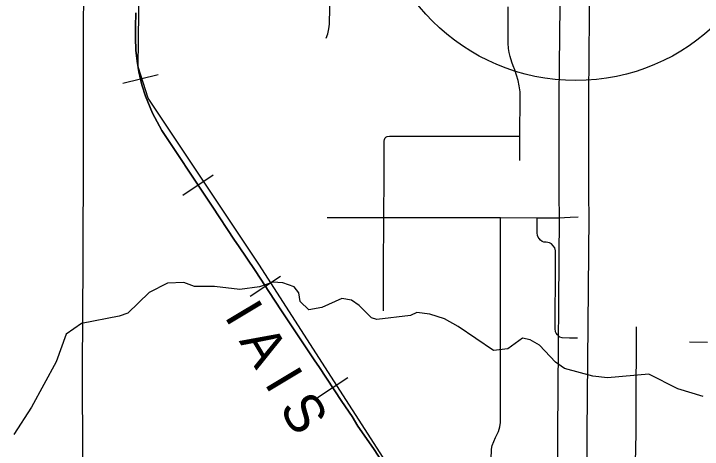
# Model space of a CAD drawing. Extents: x -1403959 to 81668, y -1400582 to 11018.
# Drawn here: x 6303.2 to 6440.3, y 8721.4 to 8808.1 of the extents above; entities that cross this region are included whole.
import ezdxf

# ---------------------------------------------------------------- set-up
doc = ezdxf.new("R2010")
doc.units = 0
for name, color, linetype in [('tdCiCityCuldesac', 7, 'Continuous'), ('tdCiSectNmbr', 7, 'Continuous'), ('tdCiSectTwpRng', 7, 'Continuous'), ('tdCoDivCarto', 7, 'Continuous'), ('tdCoSecRteBand', 7, 'Continuous'), ('tdCoSurfAsphalt', 7, 'Continuous'), ('tdCoSurfBitum', 7, 'Continuous')]:
    doc.layers.add(name, color=color, linetype=linetype)

msp = doc.modelspace()

# ---------------------------------------------------------------- linework, layer by layer
at = {"layer": 'tdCiSectNmbr'}
msp.add_lwpolyline([(6316.8, 8675.61), (6316.83, 8694.07), (6316.92, 8715.95), (6316.98, 8719.23), (6316.86, 8737.37), (6317.01, 8758.73), (6317.06, 8780.66), (6317.12, 8801.37), (6317.15, 8815.99), (6317.15, 8837.27), (6317.09, 8857.46), (6317.02, 8863.89)], dxfattribs=at)
at = {"layer": 'tdCiSectTwpRng'}
for points in [[(6365.44, 8803.2), (6365.73, 8804.09), (6365.95, 8805.05), (6366.08, 8806), (6366.28, 8815.68)], [(6404.02, 8791.51), (6404.02, 8792.55), (6403.84, 8793.75), (6403.65, 8794.82), (6403.35, 8795.85), (6402.99, 8796.9), (6402.64, 8797.71), (6402.37, 8798.45), (6402.03, 8799.54), (6401.84, 8800.39), (6401.75, 8801.18), (6401.63, 8802.23), (6401.68, 8809.45)], [(6404, 8778.87), (6404, 8783.7), (6404.02, 8791.51)], [(6376.94, 8775.69), (6376.99, 8782.7), (6377.03, 8783.03), (6377.17, 8783.37)], [(6377.17, 8783.37), (6377.33, 8783.52), (6377.59, 8783.68), (6378.03, 8783.75), (6381.98, 8783.75)], [(6381.98, 8783.75), (6404, 8783.7)], [(6376.93, 8767.55), (6376.94, 8775.63)], [(6365.64, 8767.55), (6376.93, 8767.55), (6400.13, 8767.56), (6407.43, 8767.49), (6409.61, 8767.47)], [(6376.82, 8748.97), (6376.84, 8757.17), (6376.93, 8767.55)], [(6398.28, 8719.4), (6398.34, 8721.44), (6398.46, 8722.17), (6399.15, 8723.76), (6399.71, 8724.94), (6400.02, 8725.89), (6400.1, 8726.74), (6400.13, 8767.56)], [(6407.43, 8767.49), (6407.43, 8767.49)], [(6415.5, 8743.53), (6413.88, 8743.55), (6412.39, 8743.6), (6411.96, 8743.75), (6411.72, 8743.93), (6411.47, 8744.18), (6411.25, 8744.5), (6411.11, 8744.79), (6411.04, 8745.45), (6411.08, 8757.89), (6411.09, 8760.92), (6410.95, 8761.52), (6410.64, 8761.93), (6410.3, 8762.3), (6409.9, 8762.51), (6409.23, 8762.61), (6408.76, 8762.64), (6408.41, 8762.76), (6408.12, 8763.02), (6407.84, 8763.33), (6407.62, 8763.65), (6407.5, 8763.96), (6407.45, 8764.48), (6407.43, 8767.49)], [(6409.61, 8767.47), (6411.74, 8767.48), (6413.99, 8767.62)], [(6413.99, 8767.62), (6415.6, 8767.66)], [(6427.18, 8733.73), (6427.21, 8741.1), (6427.23, 8745.8)], [(6437.76, 8742.79), (6441.35, 8742.76)], [(6427.04, 8719.37), (6427.08, 8721.02), (6427.14, 8725.24), (6427.17, 8732.18), (6427.18, 8733.73)]]:
    msp.add_lwpolyline(points, dxfattribs=at)
at = {"layer": 'tdCoDivCarto'}
for points in [[(6415.44, 8658.23), (6412.93, 8662), (6411.79, 8664.48), (6411.25, 8666.46), (6410.9, 8669.04), (6410.83, 8672.42), (6410.8, 8683.83), (6411.47, 8713.91), (6411.54, 8724.79), (6411.91, 8767.71), (6411.84, 8771.71), (6411.84, 8791.72), (6412.06, 8815.72)], [(6417.87, 8815.64), (6417.64, 8791.69), (6417.64, 8771.75), (6417.72, 8767.64), (6417.34, 8724.77), (6417.27, 8713.82), (6416.61, 8683.77), (6416.64, 8672.51), (6416.76, 8668.62), (6417.3, 8666.34), (6417.9, 8665.01), (6419.58, 8662.5)]]:
    msp.add_lwpolyline(points, dxfattribs=at)
at = {"layer": 'tdCoSecRteBand'}
for p, q in [((6324.9, 8794.24), (6331.95, 8795.97)), ((6336.89, 8771.98), (6342.92, 8776.01)), ((6350.27, 8751.88), (6356.34, 8755.85)), ((6363.67, 8731.75), (6369.74, 8735.73))]:
    msp.add_line(p, q, dxfattribs=at)
for points in [[(6408.58, 8670.42), (6352.02, 8758.22), (6329.97, 8791.27), (6328, 8797.53), (6328.6, 8846.39), (6327.94, 8883.79)], [(6379.69, 8714.18), (6374.81, 8721.61), (6371.72, 8726.04), (6370.62, 8727.95), (6368.54, 8730.94), (6363.97, 8737.91), (6363.13, 8739.03), (6360.79, 8742.58), (6356.68, 8748.76), (6355.12, 8751.08), (6351.25, 8757.01), (6347.95, 8761.88), (6347.17, 8763.02), (6342.72, 8769.79), (6339.78, 8774.19), (6334.69, 8781.86), (6332.72, 8784.84), (6330.82, 8788.32), (6329.43, 8791.65), (6328.72, 8793.91), (6328.08, 8796.51), (6327.78, 8798.61), (6327.48, 8800.84), (6327.43, 8803.27), (6327.45, 8805.48), (6327.5, 8808.23)], [(6327.5, 8808.23), (6327.45, 8805.48), (6327.43, 8803.27), (6327.48, 8800.84), (6327.78, 8798.61), (6328.08, 8796.51), (6328.72, 8793.91), (6329.43, 8791.65), (6330.82, 8788.32), (6332.72, 8784.84), (6334.69, 8781.86), (6339.78, 8774.19), (6342.72, 8769.79), (6347.17, 8763.02), (6347.95, 8761.88), (6351.25, 8757.01), (6355.12, 8751.08), (6356.68, 8748.76), (6360.79, 8742.58), (6363.13, 8739.03), (6363.97, 8737.91), (6368.54, 8730.94), (6370.62, 8727.95), (6371.72, 8726.04), (6374.81, 8721.61), (6379.69, 8714.18)]]:
    msp.add_lwpolyline(points, dxfattribs=at)
at = {"layer": 'tdCoSurfAsphalt'}
msp.add_circle((6415.13, 8835.12), 40.33, dxfattribs=at)
at = {"layer": 'tdCoSurfBitum'}
msp.add_lwpolyline([(6440.52, 8731.92), (6435.48, 8733.46), (6429.69, 8736.38), (6421.44, 8735.65), (6418.54, 8735.97), (6412.9, 8737.52), (6411.07, 8738.74), (6407.87, 8742.12), (6406.04, 8743.19), (6404.52, 8743.5), (6401.61, 8741.38), (6398.71, 8741.08), (6391.7, 8745.84), (6388.96, 8747.38), (6386.06, 8748.3), (6383.46, 8748.62), (6382.24, 8748.01), (6375.52, 8747.27), (6374.45, 8747.58), (6372.01, 8750.04), (6370.49, 8751.11), (6368.51, 8751.42), (6364.53, 8749.61), (6361.93, 8749.16), (6360.26, 8750.84), (6359.96, 8752.52), (6359.05, 8753.75), (6356.76, 8754.52), (6354.77, 8754.68), (6352.17, 8753.77), (6348.2, 8753.18), (6343.16, 8753.81), (6339.19, 8753.82), (6337.06, 8754.59), (6333.85, 8754.45), (6330.18, 8752.64), (6325.89, 8748.53), (6324.21, 8747.92), (6316.72, 8746.43), (6313.66, 8744.3), (6311.65, 8738.81), (6306.73, 8729.82), (6303.2, 8724.34)], dxfattribs=at)

# ---------------------------------------------------------------- texts
at = {"layer": 'tdCiCityCuldesac'}
msp.add_text('I A I S', height=7.738, rotation=300.9144, dxfattribs=at).set_placement((6345.02, 8747.9))

doc.saveas('drawing.dxf')
